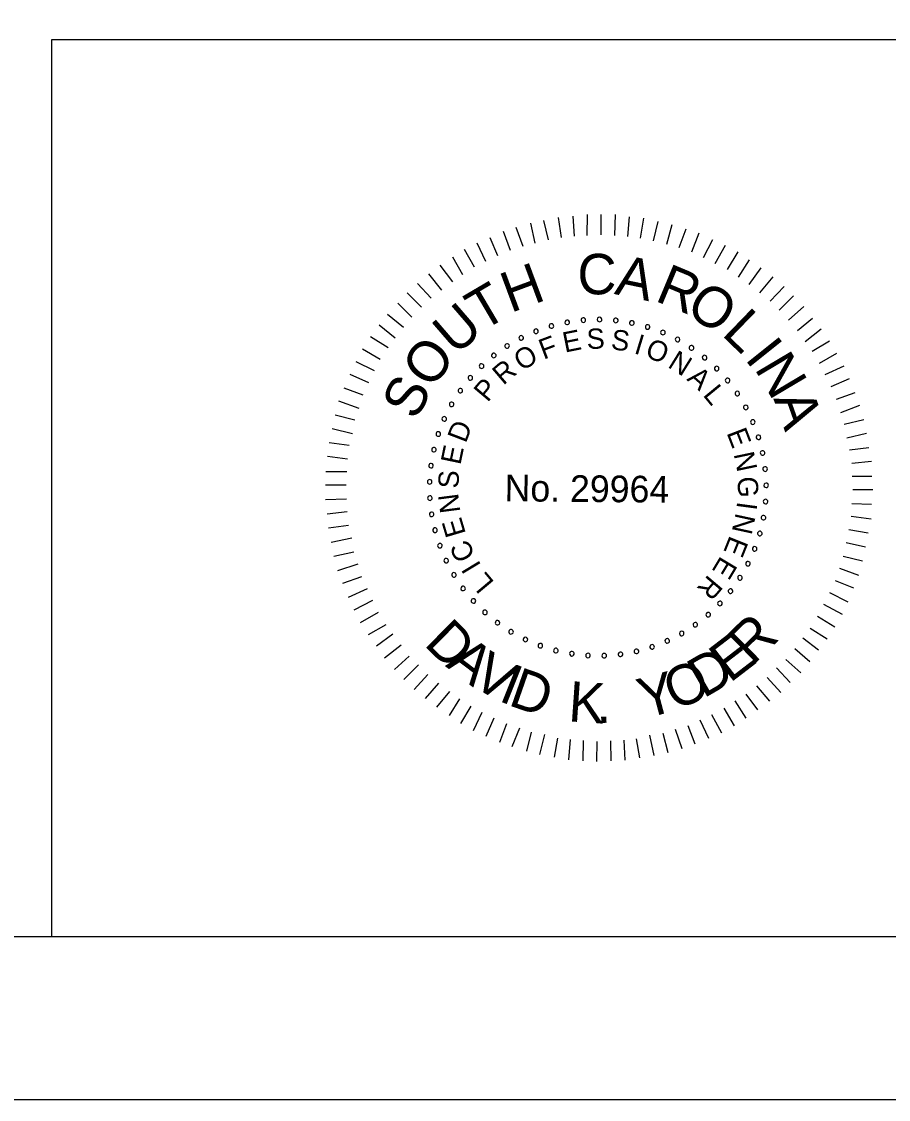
# Model space of a CAD drawing. Extents: x -55.6 to -19.5, y -100.1 to -78.1.
# Drawn here: x -33.042 to -30.386, y -100.121 to -96.816 of the extents above; entities that cross this region are included whole.
import ezdxf

# ---------------------------------------------------------------- set-up
doc = ezdxf.new("R2010")
doc.units = 0
for name, color, linetype in [('BR_BORDER LINES', 7, 'Continuous'), ('BR_TEXT', 7, 'Continuous'), ('Level 31', 7, 'Continuous')]:
    doc.layers.add(name, color=color, linetype=linetype)

msp = doc.modelspace()

# ---------------------------------------------------------------- linework, layer by layer
at = {"layer": 'BR_BORDER LINES'}
for p, q in [((-32.9495, -96.871), (-27.5843, -96.871)), ((-32.9495, -99.6211), (-32.9495, -96.871)), ((-53.7501, -99.6212), (-20.084, -99.6212))]:
    msp.add_line(p, q, dxfattribs=at)
at = {"layer": 'BR_TEXT'}
for p, q in [((-31.4273, -97.4854), (-31.4415, -97.4261)), ((-31.3878, -97.478), (-31.3967, -97.417)), ((-31.3483, -97.474), (-31.3521, -97.4131)), ((-31.3088, -97.4718), (-31.3083, -97.4074)), ((-31.2667, -97.4696), (-31.2662, -97.4078)), ((-31.2247, -97.4725), (-31.2224, -97.4081)), ((-31.1844, -97.4754), (-31.1796, -97.4145)), ((-31.1458, -97.48), (-31.135, -97.4192)), ((-31.1055, -97.4881), (-31.0913, -97.4289)), ((-31.5443, -97.5179), (-31.5653, -97.4594)), ((-31.5048, -97.5053), (-31.5266, -97.4477)), ((-31.4686, -97.4953), (-31.4818, -97.4343)), ((-31.0645, -97.4987), (-31.0485, -97.4379)), ((-31.0276, -97.5093), (-31.0057, -97.452)), ((-30.9883, -97.5225), (-30.9663, -97.4643)), ((-31.6201, -97.5516), (-31.6463, -97.4956)), ((-31.5831, -97.5347), (-31.6067, -97.4788)), ((-30.9524, -97.54), (-30.9245, -97.4844)), ((-31.6546, -97.5693), (-31.685, -97.515)), ((-30.9165, -97.5574), (-30.8851, -97.5019)), ((-30.8788, -97.5758), (-30.8466, -97.5219)), ((-31.721, -97.6143), (-31.7601, -97.5633)), ((-31.69, -97.5931), (-31.7204, -97.5387)), ((-30.8456, -97.6), (-30.8117, -97.5462)), ((-31.7547, -97.6397), (-31.7946, -97.5896)), ((-30.8123, -97.6218), (-30.7758, -97.5714)), ((-31.7876, -97.6643), (-31.8292, -97.6194)), ((-30.7799, -97.6478), (-30.7392, -97.5983)), ((-30.7484, -97.6729), (-30.7051, -97.6287)), ((-31.817, -97.6915), (-31.8612, -97.6474)), ((-30.7203, -97.7006), (-30.677, -97.6572)), ((-31.8464, -97.7222), (-31.8898, -97.6798)), ((-30.6922, -97.7318), (-30.6447, -97.6901)), ((-31.8715, -97.7538), (-31.921, -97.7147)), ((-30.665, -97.7637), (-30.6184, -97.7255)), ((-31.8975, -97.787), (-31.947, -97.7471)), ((-30.6412, -97.7974), (-30.592, -97.7583)), ((-31.9192, -97.816), (-31.973, -97.783)), ((-30.6192, -97.8267), (-30.5666, -97.7946)), ((-31.9436, -97.8527), (-31.9974, -97.8205)), ((-31.961, -97.8869), (-32.0174, -97.859)), ((-30.5972, -97.8638), (-30.5437, -97.8325)), ((-30.5794, -97.8983), (-30.5217, -97.8713)), ((-31.9785, -97.9237), (-32.0358, -97.8983)), ((-30.5617, -97.9354), (-30.5049, -97.9109)), ((-31.996, -97.9621), (-32.0541, -97.9402)), ((-30.5449, -97.9741), (-30.4881, -97.9531)), ((-32.0083, -98.0024), (-32.0699, -97.9796)), ((-30.5315, -98.0145), (-30.4738, -97.9927)), ((-32.0206, -98.0383), (-32.0815, -98.0232)), ((-30.5215, -98.0507), (-30.4613, -98.0366)), ((-32.0279, -98.0803), (-32.0904, -98.0644)), ((-30.5133, -98.0928), (-30.453, -98.0779)), ((-32.0384, -98.1163), (-32.0993, -98.108)), ((-30.5049, -98.1289), (-30.4457, -98.1217)), ((-32.0431, -98.1574), (-32.1048, -98.1501)), ((-30.4984, -98.1702), (-30.4374, -98.1638)), ((-32.046, -98.1969), (-32.1103, -98.1963)), ((-30.4971, -98.2097), (-30.437, -98.2102)), ((-32.048, -98.238), (-32.1107, -98.2375)), ((-30.4948, -98.2508), (-30.4339, -98.2513)), ((-32.0467, -98.281), (-32.111, -98.2821)), ((-32.0444, -98.3196), (-32.1062, -98.3268)), ((-30.4977, -98.2937), (-30.4377, -98.296)), ((-30.4998, -98.3324), (-30.4389, -98.3406)), ((-32.0404, -98.3608), (-32.1015, -98.3698)), ((-30.507, -98.3735), (-30.4479, -98.3834)), ((-32.0305, -98.4004), (-32.0932, -98.4136)), ((-30.5159, -98.4129), (-30.4559, -98.4271)), ((-32.024, -98.4425), (-32.085, -98.4566)), ((-30.5248, -98.4549), (-30.4649, -98.47)), ((-32.0123, -98.4795), (-32.0742, -98.5004)), ((-32.0006, -98.5182), (-32.0591, -98.5392)), ((-30.5354, -98.4917), (-30.4781, -98.5136)), ((-31.9837, -98.5552), (-32.0414, -98.5822)), ((-30.5495, -98.5302), (-30.493, -98.5521)), ((-30.5669, -98.5669), (-30.5105, -98.5948)), ((-31.9669, -98.5914), (-32.0237, -98.621)), ((-30.5853, -98.6028), (-30.528, -98.6333)), ((-31.95, -98.6285), (-32.0043, -98.6598)), ((-30.6036, -98.6396), (-30.5506, -98.6718)), ((-31.9263, -98.6656), (-31.9806, -98.6969)), ((-30.6262, -98.6763), (-30.5741, -98.7085)), ((-31.905, -98.6949), (-31.9551, -98.7314)), ((-30.6487, -98.7053), (-30.6001, -98.7426)), ((-31.8796, -98.7286), (-31.9297, -98.7677)), ((-30.6731, -98.7386), (-30.6271, -98.7784)), ((-31.855, -98.7623), (-31.8991, -98.8031)), ((-30.7008, -98.7718), (-30.6539, -98.8134)), ((-31.826, -98.7883), (-31.871, -98.8334)), ((-31.7971, -98.8185), (-31.8395, -98.8645)), ((-30.7293, -98.7973), (-30.6868, -98.8431)), ((-31.7647, -98.8445), (-31.8054, -98.8914)), ((-30.7898, -98.8526), (-30.7499, -98.9001)), ((-30.7579, -98.8271), (-30.7154, -98.8738)), ((-31.7314, -98.8706), (-31.7713, -98.9183)), ((-30.8227, -98.8781), (-30.787, -98.9264)), ((-31.7007, -98.8923), (-31.732, -98.9443)), ((-31.6657, -98.9149), (-31.697, -98.9687)), ((-30.8563, -98.8993), (-30.8233, -98.9518)), ((-31.6315, -98.9349), (-31.6586, -98.9905)), ((-31.5948, -98.9523), (-31.6193, -99.0079)), ((-30.9279, -98.9407), (-30.8975, -98.9967)), ((-30.89, -98.9213), (-30.8587, -98.9756)), ((-31.5563, -98.9698), (-31.5782, -99.0263)), ((-31.5169, -98.9822), (-31.5398, -99.0403)), ((-31.0003, -98.9744), (-30.9793, -99.0312)), ((-30.9641, -98.9576), (-30.9371, -99.0136)), ((-31.481, -98.9945), (-31.4952, -99.0536)), ((-31.4399, -99.0017), (-31.455, -99.0634)), ((-31.4005, -99.0132), (-31.4104, -99.0714)), ((-31.361, -99.0178), (-31.3659, -99.0795)), ((-31.1585, -99.0152), (-31.1487, -99.0736)), ((-31.1181, -99.0043), (-31.1049, -99.0663)), ((-31.0768, -98.9978), (-31.0618, -99.0572)), ((-31.0398, -98.9861), (-31.0189, -99.0446)), ((-31.3216, -99.0207), (-31.3221, -99.0825)), ((-31.2796, -99.0236), (-31.2801, -99.0846)), ((-31.2375, -99.0214), (-31.2363, -99.0832)), ((-31.1972, -99.0191), (-31.1934, -99.081))]:
    msp.add_line(p, q, dxfattribs=at)
for centre, start, end in [((-31.3208, -97.7314), 5.0653, 185.0653), ((-31.271, -97.7295), 359.5268, 179.5268), ((-31.271, -97.7295), 179.5268, 359.5268), ((-31.2213, -97.7324), 353.9884, 173.9884), ((-31.4659, -97.7656), 21.6807, 201.6807), ((-31.4659, -97.7656), 201.6807, 21.6807), ((-31.4187, -97.7495), 16.1422, 196.1422), ((-31.4187, -97.7495), 196.1422, 16.1422), ((-31.3702, -97.7381), 10.6038, 190.6038), ((-31.3702, -97.7381), 190.6038, 10.6038), ((-31.3208, -97.7314), 185.0653, 5.0653), ((-31.2213, -97.7324), 173.9884, 353.9884), ((-31.1721, -97.7401), 168.4499, 348.4499), ((-31.1721, -97.7401), 348.4499, 168.4499), ((-31.1238, -97.7525), 162.9114, 342.9114), ((-31.1238, -97.7525), 342.9114, 162.9114), ((-31.077, -97.7695), 337.373, 157.373), ((-31.5113, -97.7861), 27.2191, 207.2191), ((-31.5113, -97.7861), 207.2191, 27.2191), ((-31.077, -97.7695), 157.373, 337.373), ((-31.032, -97.791), 151.8345, 331.8345), ((-31.032, -97.791), 331.8345, 151.8345), ((-31.5545, -97.8109), 32.7576, 212.7576), ((-31.5545, -97.8109), 212.7576, 32.7576), ((-30.9893, -97.8167), 146.2961, 326.2961), ((-30.9893, -97.8167), 326.2961, 146.2961), ((-31.5951, -97.8398), 38.2961, 218.2961), ((-31.5951, -97.8398), 218.2961, 38.2961), ((-30.9493, -97.8464), 140.7576, 320.7576), ((-30.9493, -97.8464), 320.7576, 140.7576), ((-31.6327, -97.8725), 43.8345, 223.8345), ((-31.6327, -97.8725), 223.8345, 43.8345), ((-30.9123, -97.8798), 135.2191, 315.2191), ((-30.9123, -97.8798), 315.2191, 135.2191), ((-31.667, -97.9086), 49.373, 229.373), ((-31.667, -97.9086), 229.373, 49.373), ((-30.8788, -97.9167), 129.6807, 309.6807), ((-30.8788, -97.9167), 309.6807, 129.6807), ((-31.6977, -97.9479), 54.9114, 234.9114), ((-31.6977, -97.9479), 234.9114, 54.9114), ((-30.8489, -97.9566), 124.1422, 304.1422), ((-30.8489, -97.9566), 304.1422, 124.1422), ((-31.7244, -97.9899), 60.4499, 240.4499), ((-31.7244, -97.9899), 240.4499, 60.4499), ((-30.8231, -97.9992), 118.6038, 298.6038), ((-30.8231, -97.9992), 298.6038, 118.6038), ((-31.747, -98.0344), 65.9884, 245.9884), ((-31.747, -98.0344), 245.9884, 65.9884), ((-30.8014, -98.0441), 113.0653, 293.0653), ((-30.8014, -98.0441), 293.0653, 113.0653), ((-31.7651, -98.0808), 71.5268, 251.5268), ((-31.7651, -98.0808), 251.5268, 71.5268), ((-30.7842, -98.0908), 107.5268, 287.5268), ((-30.7842, -98.0908), 287.5268, 107.5268), ((-31.7787, -98.1287), 77.0653, 257.0653), ((-31.7787, -98.1287), 257.0653, 77.0653), ((-30.7716, -98.139), 101.9884, 281.9884), ((-30.7716, -98.139), 281.9884, 101.9884), ((-31.7876, -98.1778), 82.6038, 262.6038), ((-31.7876, -98.1778), 262.6038, 82.6038), ((-30.7638, -98.1882), 96.4499, 276.4499), ((-30.7638, -98.1882), 276.4499, 96.4499), ((-31.7917, -98.2274), 88.1422, 268.1422), ((-31.7917, -98.2274), 268.1422, 88.1422), ((-30.7607, -98.238), 90.9114, 270.9114), ((-30.7607, -98.238), 270.9114, 90.9114), ((-31.791, -98.2772), 93.6807, 273.6807), ((-31.791, -98.2772), 273.6807, 93.6807), ((-30.7624, -98.2878), 85.373, 265.373), ((-30.7624, -98.2878), 265.373, 85.373), ((-31.7855, -98.3268), 99.2191, 279.2191), ((-31.7855, -98.3268), 279.2191, 99.2191), ((-30.7689, -98.3372), 79.8345, 259.8345), ((-30.7689, -98.3372), 259.8345, 79.8345), ((-31.7753, -98.3755), 104.7576, 284.7576), ((-31.7753, -98.3755), 284.7576, 104.7576), ((-30.7801, -98.3857), 74.2961, 254.2961), ((-30.7801, -98.3857), 254.2961, 74.2961), ((-31.7604, -98.4231), 110.2961, 290.2961), ((-31.7604, -98.4231), 290.2961, 110.2961), ((-30.796, -98.433), 68.7576, 248.7576), ((-30.796, -98.433), 248.7576, 68.7576), ((-31.7409, -98.469), 115.8345, 295.8345), ((-31.7409, -98.469), 295.8345, 115.8345), ((-30.8164, -98.4784), 63.2191, 243.2191), ((-30.8164, -98.4784), 243.2191, 63.2191), ((-31.7171, -98.5128), 121.373, 301.373), ((-31.7171, -98.5128), 301.373, 121.373), ((-30.841, -98.5217), 57.6807, 237.6807), ((-30.841, -98.5217), 237.6807, 57.6807), ((-31.6893, -98.5541), 126.9114, 306.9114), ((-31.6893, -98.5541), 306.9114, 126.9114), ((-30.8698, -98.5625), 52.1422, 232.1422), ((-31.6575, -98.5925), 132.4499, 312.4499), ((-31.6575, -98.5925), 312.4499, 132.4499), ((-30.8698, -98.5625), 232.1422, 52.1422), ((-31.6222, -98.6276), 317.9884, 137.9884), ((-30.9023, -98.6002), 46.6038, 226.6038), ((-30.9023, -98.6002), 226.6038, 46.6038), ((-31.6222, -98.6276), 137.9884, 317.9884), ((-31.5837, -98.6592), 143.5268, 323.5268), ((-31.5837, -98.6592), 323.5268, 143.5268), ((-30.9383, -98.6347), 41.0653, 221.0653), ((-30.9383, -98.6347), 221.0653, 41.0653), ((-31.5423, -98.687), 149.0653, 329.0653), ((-31.5423, -98.687), 329.0653, 149.0653), ((-31.0194, -98.6923), 29.9884, 209.9884), ((-30.9775, -98.6655), 35.5268, 215.5268), ((-30.9775, -98.6655), 215.5268, 35.5268), ((-31.4984, -98.7106), 154.6038, 334.6038), ((-31.4984, -98.7106), 334.6038, 154.6038), ((-31.0638, -98.715), 24.4499, 204.4499), ((-31.0638, -98.715), 204.4499, 24.4499), ((-31.0194, -98.6923), 209.9884, 29.9884), ((-31.4525, -98.7298), 160.1422, 340.1422), ((-31.4525, -98.7298), 340.1422, 160.1422), ((-31.4049, -98.7446), 165.6807, 345.6807), ((-31.4049, -98.7446), 345.6807, 165.6807), ((-31.356, -98.7547), 171.2191, 351.2191), ((-31.356, -98.7547), 351.2191, 171.2191), ((-31.3065, -98.76), 356.7576, 176.7576), ((-31.2567, -98.7605), 2.2961, 182.2961), ((-31.207, -98.7562), 7.8345, 187.8345), ((-31.158, -98.7471), 13.373, 193.373), ((-31.158, -98.7471), 193.373, 13.373), ((-31.1101, -98.7334), 18.9114, 198.9114), ((-31.1101, -98.7334), 198.9114, 18.9114), ((-31.3065, -98.76), 176.7576, 356.7576), ((-31.2567, -98.7605), 182.2961, 2.2961), ((-31.207, -98.7562), 187.8345, 7.8345)]:
    msp.add_arc(centre, 0.00701, start, end, dxfattribs=at)
at = {"layer": 'Level 31'}
msp.add_lwpolyline([(-55.5834, -100.1211), (-19.5834, -100.1211), (-19.5834, -78.1211), (-55.5834, -78.1211)], close=True, dxfattribs=at)

# ---------------------------------------------------------------- texts
at = {"layer": 'BR_TEXT'}
for s, height, rotation, p in [('C', 0.1241, 359.5482, (-31.3395, -97.6519)), ('H', 0.1241, 20.3637, (-31.5439, -97.7102)), ('A', 0.1241, 348.1981, (-31.2281, -97.6511)), ('R', 0.1241, 337.4344, (-31.1048, -97.671)), ('T', 0.1241, 30.4992, (-31.6318, -97.7677)), ('O', 0.1239, 326.5869, (-31.0126, -97.7077)), ('U', 0.1241, 40.8022, (-31.713, -97.8425)), ('L', 0.1241, 315.9488, (-30.9, -97.7755)), ('E', 0.0622, 11.4103, (-31.3775, -97.8314)), ('S', 0.0622, 2.208, (-31.3097, -97.8204)), ('S', 0.0622, 352.6608, (-31.2384, -97.8206)), ('O', 0.1241, 52.0267, (-31.7876, -97.9464)), ('F', 0.0622, 20.6127, (-31.4427, -97.8531)), ('I', 0.0622, 343.1136, (-31.1682, -97.8327)), ('O', 0.0622, 338.4392, (-31.1347, -97.8428)), ('I', 0.1241, 308.6613, (-30.8287, -97.8498)), ('O', 0.0622, 30.8477, (-31.51, -97.8891)), ('N', 0.0622, 328.2042, (-31.0651, -97.8742)), ('N', 0.1241, 300.7037, (-30.7981, -97.8792)), ('R', 0.0622, 40.3949, (-31.5662, -97.933)), ('A', 0.0622, 318.657, (-31.0061, -97.9142)), ('S', 0.1239, 63.2511, (-31.8329, -98.042)), ('P', 0.0622, 49.9421, (-31.6143, -97.9856)), ('L', 0.0622, 309.4546, (-30.9564, -97.9615)), ('A', 0.1241, 289.4792, (-30.7388, -97.9722)), ('D', 0.0622, 69.0364, (-31.6812, -98.1109)), ('E', 0.0622, 291.049, (-30.8825, -98.0769)), ('E', 0.0622, 78.2388, (-31.6978, -98.1775)), ('N', 0.0622, 281.8466, (-30.8603, -98.1419)), ('S', 0.0622, 87.786, (-31.7035, -98.2486)), ('No. 29964', 0.08175, 359.5268, (-31.5624, -98.287)), ('G', 0.0622, 272.2995, (-30.8486, -98.2122)), ('N', 0.0622, 97.3332, (-31.6973, -98.3196)), ('I', 0.0622, 262.4084, (-30.8489, -98.286)), ('E', 0.0622, 106.5355, (-31.6803, -98.3861)), ('N', 0.0622, 257.7339, (-30.8535, -98.3206)), ('C', 0.0622, 116.4266, (-31.6504, -98.4536)), ('E', 0.0622, 248.1867, (-30.8715, -98.3896)), ('I', 0.0622, 121.1011, (-31.6324, -98.4835)), ('E', 0.0622, 238.9844, (-30.8994, -98.4523)), ('L', 0.0622, 129.9595, (-31.5917, -98.5357)), ('R', 0.0622, 229.782, (-30.9371, -98.5098)), ('D', 0.1236, 315.4053, (-31.8122, -98.7263)), ('R', 0.1236, 44.5947, (-30.8013, -98.7919)), ('E', 0.1236, 37.5339, (-30.872, -98.8458)), ('A', 0.1236, 322.8377, (-31.7456, -98.7919)), ('V', 0.1236, 330.5179, (-31.6685, -98.8501)), ('D', 0.1236, 30.1015, (-30.9529, -98.8927)), ('O', 0.1236, 22.4212, (-31.0421, -98.9297)), ('I', 0.1236, 338.1981, (-31.5842, -98.8975)), ('D', 0.1236, 340.7995, (-31.5544, -98.9109)), ('Y', 0.1236, 14.8649, (-31.134, -98.9542)), ('K', 0.1236, 356.098, (-31.3691, -98.9615)), ('.', 0.1236, 3.1588, (-31.2805, -98.9678))]:
    msp.add_text(s, height=height, rotation=rotation, dxfattribs=at).set_placement(p)

doc.saveas('drawing.dxf')
